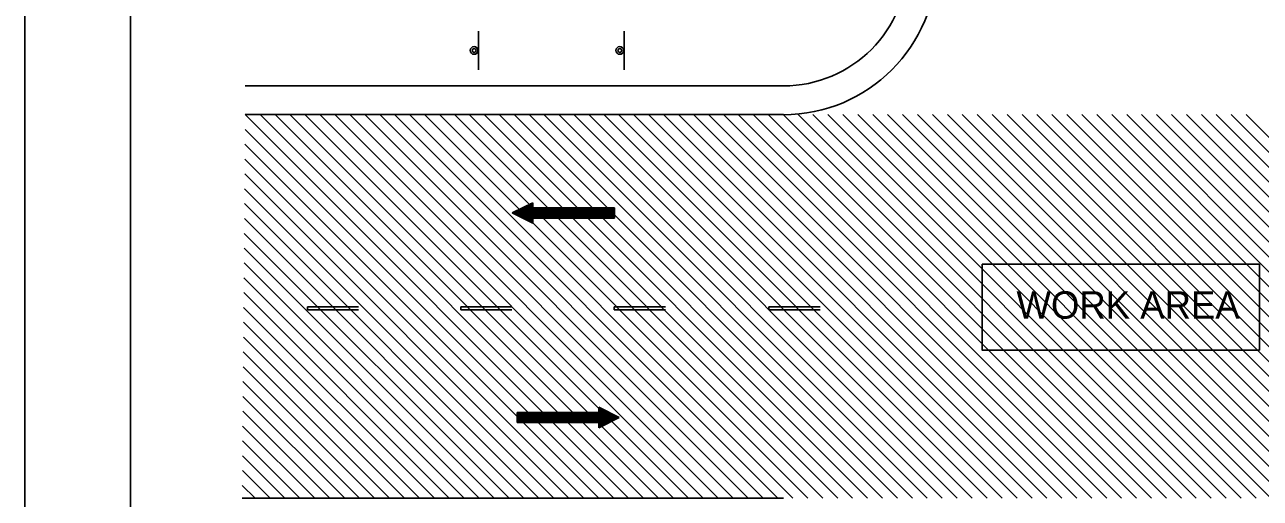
# Model space of a CAD drawing. Extents: x 1833 to 2049, y 205 to 484.
# Drawn here: x 1833.5 to 1950.4, y 364.1 to 408.9 of the extents above; entities that cross this region are included whole.
import ezdxf

# ---------------------------------------------------------------- set-up
doc = ezdxf.new("R2010")
doc.units = 0
for name, color, linetype in [('Level 10', 7, 'Continuous'), ('Level 2', 7, 'Continuous'), ('Level 44', 7, 'Continuous'), ('Level 60', 7, 'Continuous')]:
    doc.layers.add(name, color=color, linetype=linetype)

msp = doc.modelspace()

# ---------------------------------------------------------------- linework, layer by layer
at = {"layer": 'Level 10'}
for p, q in [((1854.33, 403.08), (1905.27, 403.08)), ((1854.33, 400.36), (1905.27, 400.36)), ((1890.62, 364.07), (1854.33, 400.36)), ((1892.04, 364.07), (1855.74, 400.36)), ((1893.45, 364.07), (1857.16, 400.36)), ((1894.86, 364.07), (1858.57, 400.36)), ((1896.28, 364.07), (1859.99, 400.36)), ((1897.69, 364.07), (1861.4, 400.36)), ((1899.11, 364.07), (1862.82, 400.36)), ((1900.52, 364.07), (1864.23, 400.36)), ((1901.93, 364.07), (1865.64, 400.36)), ((1903.35, 364.07), (1867.06, 400.36)), ((1904.76, 364.07), (1868.47, 400.36)), ((1906.18, 364.07), (1869.89, 400.36)), ((1907.59, 364.07), (1871.3, 400.36)), ((1909.01, 364.07), (1872.72, 400.36)), ((1910.42, 364.07), (1874.13, 400.36)), ((1911.83, 364.07), (1875.54, 400.36)), ((1913.25, 364.07), (1876.96, 400.36)), ((1914.66, 364.07), (1878.37, 400.36)), ((1916.08, 364.07), (1879.79, 400.36)), ((1917.49, 364.07), (1881.2, 400.36)), ((1918.9, 364.07), (1882.61, 400.36)), ((1920.32, 364.07), (1884.03, 400.36)), ((1921.73, 364.07), (1885.44, 400.36)), ((1923.15, 364.07), (1886.86, 400.36)), ((1924.56, 364.07), (1888.27, 400.36)), ((1925.98, 364.07), (1889.68, 400.36)), ((1927.39, 364.07), (1891.1, 400.36)), ((1928.81, 364.07), (1892.51, 400.36)), ((1930.22, 364.07), (1893.93, 400.36)), ((1931.63, 364.07), (1895.34, 400.36)), ((1933.05, 364.07), (1896.76, 400.36)), ((1934.46, 364.07), (1898.17, 400.36)), ((1935.88, 364.07), (1899.59, 400.36)), ((1937.29, 364.07), (1901, 400.36)), ((1938.7, 364.07), (1902.41, 400.36)), ((1940.12, 364.07), (1903.83, 400.36)), ((1941.53, 364.07), (1905.24, 400.36)), ((1942.95, 364.07), (1906.66, 400.36)), ((1944.36, 364.07), (1908.07, 400.36)), ((1945.78, 364.07), (1909.48, 400.36)), ((1947.19, 364.07), (1910.9, 400.36)), ((1948.6, 364.07), (1912.31, 400.36)), ((1950.02, 364.07), (1913.73, 400.36)), ((1951.43, 364.07), (1915.14, 400.36)), ((1952.85, 364.07), (1916.56, 400.36)), ((1954.26, 364.07), (1917.97, 400.36)), ((1955.67, 364.07), (1919.38, 400.36)), ((1957.09, 364.07), (1920.8, 400.36)), ((1958.5, 364.07), (1922.21, 400.36)), ((1959.92, 364.07), (1923.63, 400.36)), ((1961.33, 364.07), (1925.04, 400.36)), ((1962.75, 364.07), (1926.45, 400.36)), ((1964.16, 364.07), (1927.87, 400.36)), ((1965.57, 364.07), (1929.28, 400.36)), ((1966.99, 364.07), (1930.7, 400.36)), ((1968.4, 364.07), (1932.11, 400.36)), ((1969.82, 364.07), (1933.53, 400.36)), ((1971.23, 364.07), (1934.94, 400.36)), ((1972.64, 364.07), (1936.35, 400.36)), ((1974.06, 364.07), (1937.77, 400.36)), ((1975.47, 364.07), (1939.18, 400.36)), ((1976.89, 364.07), (1940.6, 400.36)), ((1978.3, 364.07), (1942.01, 400.36)), ((1979.72, 364.07), (1943.42, 400.36)), ((1981.13, 364.07), (1944.84, 400.36)), ((1982.55, 364.07), (1946.25, 400.36)), ((1983.96, 364.07), (1947.67, 400.36)), ((1985.37, 364.07), (1949.08, 400.36)), ((1889.21, 364.07), (1854.32, 398.95)), ((1887.79, 364.07), (1854.31, 397.55)), ((1886.38, 364.07), (1854.3, 396.15)), ((1884.96, 364.07), (1854.29, 394.75)), ((1883.55, 364.07), (1854.27, 393.34)), ((1882.14, 364.07), (1854.26, 391.94)), ((1879.61, 391.06), (1881.55, 392.03)), ((1881.31, 391.91), (1881.55, 391.91)), ((1881.55, 391.55), (1881.55, 392.03)), ((1879.61, 391.06), (1889.29, 391.06)), ((1879.61, 391.06), (1881.55, 390.1)), ((1879.86, 391.18), (1889.29, 391.18)), ((1879.86, 390.94), (1889.29, 390.94)), ((1880.1, 391.3), (1889.29, 391.3)), ((1880.1, 390.82), (1889.29, 390.82)), ((1880.34, 391.43), (1889.29, 391.43)), ((1880.34, 390.7), (1889.29, 390.7)), ((1880.58, 391.55), (1889.29, 391.55)), ((1880.82, 391.67), (1881.55, 391.67)), ((1881.07, 391.79), (1881.55, 391.79)), ((1881.55, 391.55), (1889.29, 391.55)), ((1889.29, 390.58), (1889.29, 391.55)), ((1880.72, 364.07), (1854.25, 390.54)), ((1880.58, 390.58), (1889.29, 390.58)), ((1880.82, 390.46), (1881.55, 390.46)), ((1881.07, 390.34), (1881.55, 390.34)), ((1881.31, 390.22), (1881.55, 390.22)), ((1881.55, 390.58), (1889.29, 390.58)), ((1881.55, 390.1), (1881.55, 390.58)), ((1879.31, 364.07), (1854.24, 389.13)), ((1877.89, 364.07), (1854.23, 387.73)), ((1876.48, 364.07), (1854.22, 386.33)), ((1875.07, 364.07), (1854.2, 384.93)), ((1873.65, 364.07), (1854.19, 383.52)), ((1872.24, 364.07), (1854.18, 382.12)), ((1870.82, 364.07), (1854.17, 380.72)), ((1869.41, 364.07), (1854.16, 379.31)), ((1867.99, 364.07), (1854.15, 377.91)), ((1866.58, 364.07), (1854.14, 376.51)), ((1865.16, 364.07), (1854.12, 375.11)), ((1863.75, 364.07), (1854.11, 373.7)), ((1862.34, 364.07), (1854.1, 372.3)), ((1887.8, 372.18), (1880.06, 372.18)), ((1880.06, 372.18), (1880.06, 371.22)), ((1888.77, 372.18), (1880.06, 372.18)), ((1889.01, 372.06), (1880.06, 372.06)), ((1889.25, 371.94), (1880.06, 371.94)), ((1889.74, 371.7), (1887.8, 372.67)), ((1887.8, 372.67), (1887.8, 372.18)), ((1888.05, 372.55), (1887.8, 372.55)), ((1888.29, 372.43), (1887.8, 372.43)), ((1888.53, 372.3), (1887.8, 372.3)), ((1860.92, 364.07), (1854.09, 370.9)), ((1889.5, 371.82), (1880.06, 371.82)), ((1889.74, 371.7), (1880.06, 371.7)), ((1889.5, 371.58), (1880.06, 371.58)), ((1889.25, 371.46), (1880.06, 371.46)), ((1889.01, 371.34), (1880.06, 371.34)), ((1887.8, 371.22), (1880.06, 371.22)), ((1888.77, 371.22), (1880.06, 371.22)), ((1889.74, 371.7), (1887.8, 370.73)), ((1887.8, 371.22), (1887.8, 370.73)), ((1888.53, 371.09), (1887.8, 371.09)), ((1888.29, 370.98), (1887.8, 370.98)), ((1888.05, 370.85), (1887.8, 370.85)), ((1859.51, 364.07), (1854.08, 369.49)), ((1858.09, 364.07), (1854.07, 368.09)), ((1856.68, 364.07), (1854.06, 366.69)), ((1855.27, 364.07), (1854.05, 365.29)), ((1854.04, 364.07), (1905.27, 364.07))]:
    msp.add_line(p, q, dxfattribs=at)
msp.add_lwpolyline([(1924.08, 386.21), (1950.34, 386.21), (1950.34, 378.08), (1924.08, 378.08)], close=True, dxfattribs=at)
for radius in [14.52, 11.79]:
    msp.add_arc((1905.27, 414.87), radius, 270, 0, dxfattribs=at)
at = {"layer": 'Level 2'}
for p, q in [((1865.07, 382.19), (1860.23, 382.19)), ((1860.23, 382.19), (1860.23, 381.9)), ((1860.23, 381.9), (1865.07, 381.9)), ((1879.58, 382.19), (1874.74, 382.19)), ((1874.74, 382.19), (1874.74, 381.9)), ((1874.74, 381.9), (1879.58, 381.9)), ((1894.1, 382.19), (1889.26, 382.19)), ((1889.26, 382.19), (1889.26, 381.9)), ((1889.26, 381.9), (1894.1, 381.9)), ((1908.75, 382.19), (1903.91, 382.19)), ((1903.91, 382.19), (1903.91, 381.9)), ((1903.91, 381.9), (1908.75, 381.9))]:
    msp.add_line(p, q, dxfattribs=at)
at = {"layer": 'Level 44'}
for p, q in [((1876.4, 404.61), (1876.4, 408.24)), ((1890.2, 404.61), (1890.2, 408.24))]:
    msp.add_line(p, q, dxfattribs=at)
for centre, radius in [((1876, 406.43), 0.363), ((1876, 406.43), 0.181), ((1889.79, 406.43), 0.363), ((1889.79, 406.43), 0.181)]:
    msp.add_circle(centre, radius, dxfattribs=at)
at = {"layer": 'Level 60'}
for points in [[(2049.46, 484.39), (1833.46, 484.39), (1833.46, 205.39), (2049.46, 205.39)], [(2030.33, 473.58), (1843.46, 473.58), (1843.46, 216.2), (2030.33, 216.2)]]:
    msp.add_lwpolyline(points, close=True, dxfattribs=at)

# ---------------------------------------------------------------- texts
at = {"layer": 'Level 10'}
msp.add_text('WORK AREA', height=2.585, dxfattribs=at).set_placement((1927.34, 381.06))

doc.saveas('drawing.dxf')
